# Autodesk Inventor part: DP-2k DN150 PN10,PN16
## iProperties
Created: 2009-08
Part Number: DP-2k DN150 PN10,PN16
Document SubType Name: Modelowanie
Designer: Marcin Pyzik
Author: Marcin Pyzik
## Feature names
1. Wyciągnięcie proste1 [Extrusion]
2. Faza1 [Chamfer]
3. Bryła wyprowadzona1 [Tagging]
